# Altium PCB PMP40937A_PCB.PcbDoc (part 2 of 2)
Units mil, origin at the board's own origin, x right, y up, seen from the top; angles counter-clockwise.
Board outline 1377.95 x 1377.95 mil, 2 copper layers (Top Layer, Bottom Layer), stack 62 mil thick; 90 components, 42 nets, 235 pads, 300 vias.
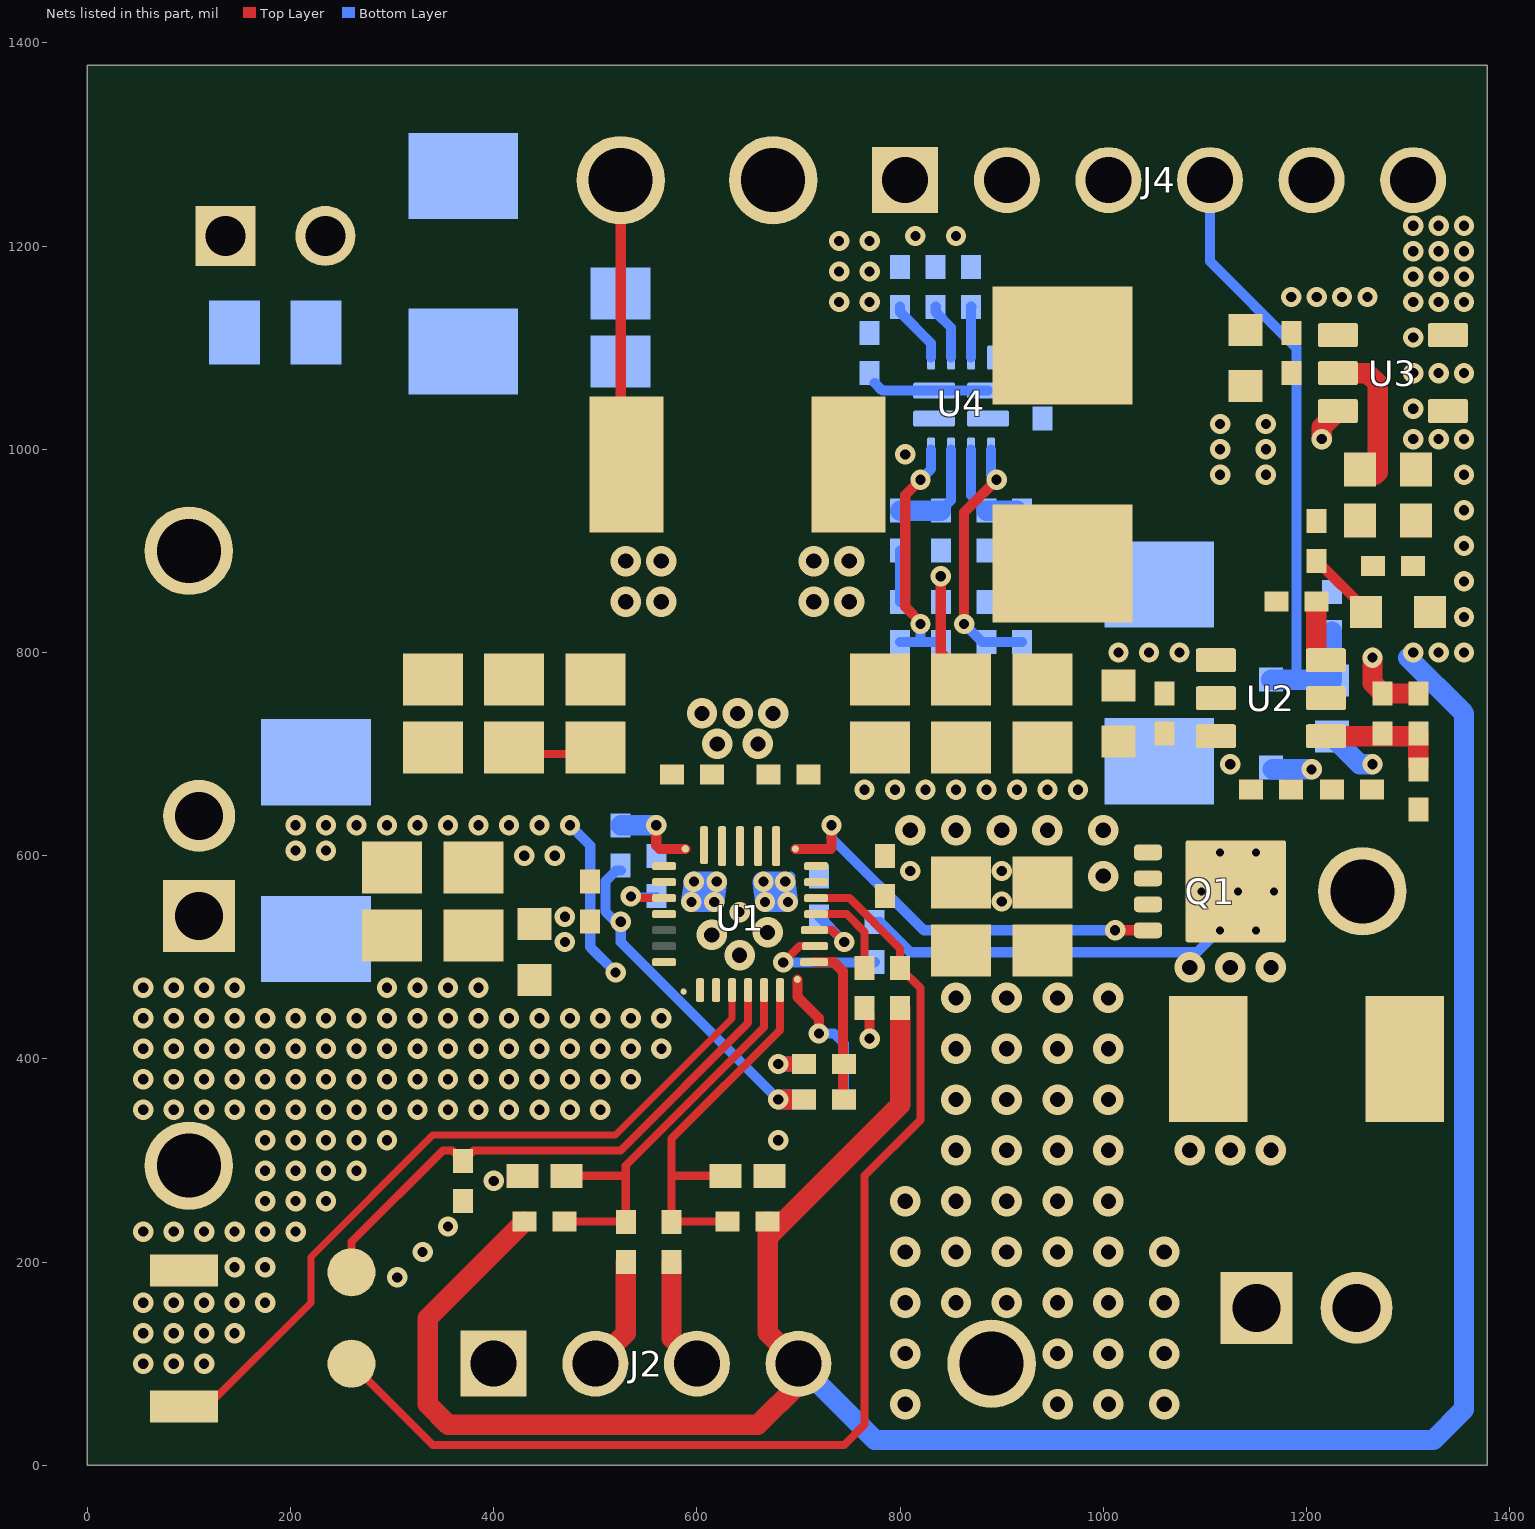
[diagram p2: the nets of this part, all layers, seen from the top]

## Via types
v1: diameter 20, hole 10, Top Layer to Bottom Layer, tented both sides, 199 vias
v2: diameter 30, hole 15, Top Layer to Bottom Layer, tented both sides, 63 vias
v3: diameter 20, hole 10, Top Layer to Bottom Layer, tented top, 13 vias
v4: diameter 19.68, hole 7.87, Top Layer to Bottom Layer, 6 vias
v5: diameter 20, hole 10, Top Layer to Bottom Layer, tented bottom, 6 vias
v6: diameter 30, hole 15, Top Layer to Bottom Layer, tented top, 6 vias
v7: diameter 20, hole 10, Top Layer to Bottom Layer, 4 vias
v8: diameter 19.68, hole 7.87, Top Layer to Bottom Layer, tented both sides, 1 vias
v9: diameter 30, hole 15, Top Layer to Bottom Layer, tented bottom, 1 vias
v10: diameter 30, hole 15, Top Layer to Bottom Layer, 1 vias

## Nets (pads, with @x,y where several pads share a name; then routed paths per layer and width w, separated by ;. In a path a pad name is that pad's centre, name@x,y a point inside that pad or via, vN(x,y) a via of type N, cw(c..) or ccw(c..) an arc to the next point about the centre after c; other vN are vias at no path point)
3.3V: C25.1 C26.1 C27.2 D8.2 J2.4 J4.6 R5.1 R6.1 R11.1 U3.4 U3.5 | length 2522.8
  Top Layer w20: R6.1@430.32,240 335,144.68 335,60 355,40 660,40 700,80 J2.4@700,100 669.68,130.32 669.68,224.68 ; R5.1@669.68,240 669.68,224.68 ; R11.1@800,450.32 800,355 669.68,224.68
  Bottom Layer w20: J2.4@700,100 775,25 1325,25 1355,55 1355,740 v1@1300,795
  other v1: 1305,800 1330,800 1355,835 1355,870 1355,905 1355,940 1355,975 1305,1010 1330,1010 1355,1010 1305,1040 1305,1075 1330,1075 1355,1075 1305,1110 1305,1145 1330,1145 1355,1145 1305,1170 1330,1170 1305,1195 1330,1195 1305,1220 1330,1220 1355,1220
  other v3: 1355,800
  other v7: 1355,1170 1355,1195
5V: C22.1 C23.1 C24.2 J4.5 L2.2 R21.1 U3.1 U3.3 | length 112.8
  Top Layer w10: U3.3@1230.87,1033.46 U3.3@1230.87,1037.6
  Top Layer w20: v1(1215,1010) 1215,1021.73 U3.3@1230.87,1037.6 ; v3(1265,795) 1265,769.68 C22.1@1275,759.68 R21.1@1310,759.68
  other v1: 1235,1150
  other v3: 1260,1150
  other v5: 1185,1150 1210,1150
CE: pad.1@260,190 R7.1 U1.13 | length 550.8
  Top Layer w8: pad.1@260,190 260,220 350,310 359.37,310 R7.1@369.68,299.68 ; R7.1@370,299.68 R7.1@369.68,299.68 ; U1.13@650.37,467.7 650.37,435.37 525,310 380,310 R7.1@369.68,299.68
INT: pad.2@260,100 R11.2 U1.21 | length 1149.2
  Top Layer w8: pad.2@260,100 340,20 745,20 765,40 765,285 820,340 820,469.69 R11.2@800,489.69 800,508.38 750.14,558.25 U1.21@717.3,558.25
NetC9_1: C9.1 L1.2 TP3.1 U1.28 | length 369.1
  Top Layer w10: TP3.1@525,1265 525,990.75 L1.2@530.75,985
  Bottom Layer w10: v1@593.12,577 v1@594.5,577
  Bottom Layer w20: v1(594.5,554.5) v1(597,574.5) v1(619.5,574.5) v1(617,554.5) v1(594.5,554.5)
  other v2: 530,850 565,850 530,890 565,890
NetC9_2: C9.2 U1.4 | length 62.8
  Top Layer w8: v1@530,558.25 U1.4@567.7,558.25
  Bottom Layer w8: v1(535,560) 559.69,560 C9.2@560,560.31
NetC10_1: C10.1 L1.1 U1.26 | length 92.6
  Bottom Layer w10: v1(687,574.5) v1@692.18,579.68
  Bottom Layer w20: v1@664.5,574.5 v1(667,554.5) v1(689.5,554.5) v1(687,574.5) v1@664.5,574.5
  other v1: 665.5,574.5
  other v2: 715,850 715,890 750,890
  other v6: 750,850
NetC10_2: C10.2 U1.19 | length 70.3
  Top Layer w8: U1.19@715.73,526.75 732.99,526.75 744.75,515 v1(745,515)
  Bottom Layer w10: C10.2@720,540.31 745.31,515 v1(745,515)
NetC11_2: C11.2 C12.1 C13.1 Q1.1 Q1.2 Q1.3 U1.22 U1.23
  other v1: 900,555 810,585 900,585
  other v2: 810,625 945,625 1000,625
  other v6: 1000,580 855,625 900,625
NetC21_1: C21.1 L2.1 U2.2
NetC21_2: C21.2 U2.6 | length 53.1
  Top Layer w20: U2.6@1209.68,791.85 C21.2@1209.68,845
NetC22_2: C22.2 R20.2 R21.2 U2.4 | length 113.8
  Top Layer w20: U2.4@1219.13,717.6 R21.2@1302.28,717.6 ; R20.2@1310,689.69 R21.2@1310,720.31
NetC31_2: C31.2 U4.11 | length 50.1
  Bottom Layer w10: U4.11@869.84,1090.28 869.84,1140.16 C31.2@870,1140.31
NetC32_2: C32.2 C33.1 J3.2 pad.1@370,1096.26 pad.2@225,1115 U4.1 U4.8 | length 114.7
  Bottom Layer w10: C32.2@775,1065.32 782.52,1057.8 U4.8@833.43,1057.8 U4.1@886.57,1057.8
NetD5_1: D5.1 R4.2 R5.2 U1.15 | length 380.6
  Top Layer w8: R4.2@575,239.69 575,285 ; R4.2@575.31,240 R5.2@630.31,240 ; D5.1@628.35,285 575,285 ; U1.15@681.87,467.7 681.87,428.74 681,427.87 681,427.62 575,321.62 575,285
NetD6_1: D6.1 R3.2 R6.2 U1.14 | length 402.7
  Top Layer w8: R6.2@469.69,240 R3.2@529.69,240 ; D6.1@471.65,285 530,285 ; R3.2@530,239.69 530,285 ; U1.14@666.12,467.7 666.12,431.12 530,295 530,285
NetD7_2: D7.2 R17.1 R18.2 U2.5 | length 38.3
  Bottom Layer w20: D7.2@1166.69,685 v1(1205,685)
NetD8_1: D8.1 R22.1 | length 71.2
  Top Layer w10: R22.1@1210.16,890.32 D8.1@1260.47,840
NetF1_1: F1.1 J5.2
NetJ2_2: J2.2 R3.1 | length 112.7
  Top Layer w20: J2.2@500,100 530,130 R3.1@530,200.32
NetJ2_3: J2.3 R4.1 | length 110.7
  Top Layer w20: R4.1@575,200.32 575,125 J2.3@600,100
NetQ1_4: Q1.4 U1.24 | length 421
  Top Layer w10: U1.24@696.88,606.72 731.72,606.72 732.5,607.5 v3(732.5,630) ; v3(1011.61,526.61) Q1.4@1044.96,526.61
  Bottom Layer w10: v3(732.5,630) 732.5,617.5 823.39,526.61 v3(1011.61,526.61)
NetR1_1: R1.1 R2.2 U1.17 | length 158.3
  Top Layer w10: U1.17@715.33,495.26 734.74,495.26 743.62,486.38 R1.1@743.62,360
NetR8_1: R8.1 U1.20 | length 90.3
  Top Layer w8: U1.20@717.3,542.5 747.5,542.5 765,525 R8.1@765,489.68
NetR9_1: R9.1 U1.18 | length 128.1
  Top Layer w8: v1(685,495) 701,511 U1.18@716.32,511
  Bottom Layer w10: v1(685,495) 774.68,495 R9.1@775,495.32
NetR10_2: R10.2 U1.1 | length 80.5
  Top Layer w10: v3@560,625 560,610 563.28,606.72 U1.1@588.61,606.72
  Bottom Layer w10: v3@559.69,624.69 v3@560,625
  Bottom Layer w20: R10.2@525,629.69 525.31,630 v3(560,630)
NetR12_1: R12.1 R13.2 U1.16 | length 146.1
  Top Layer w10: U1.16@698.85,478.28 698.85,461.15 720,440 v1(720,425)
  Bottom Layer w10: v1(720,425) 735,425 744.68,415.32 R12.1@744.68,360
NetR24_2: R24.2 R25.1 U4.6 | length 249.2
  Top Layer w10: v1@820,825 v1(820,828) 820,830 805,845 805,955 v1(820,970)
  Bottom Layer w10: R24.2@800,810.31 820,810.31 ; v1(820,828) 820,810.31 ; v1(820,970) 830.47,980.47 U4.6@830.47,999.72 ; R25.1@840,810.32 820,810.31
NetR26_2: R26.2 R27.1 U4.3 | length 251.6
  Top Layer w10: v1(863,828) 863,938 v1(895,970)
  Bottom Layer w10: v1(863,828) 880.68,810.32 R27.1@885,810.32 R26.2@920,810.31 ; U4.3@889.53,999.72 889.53,975.47 v1(895,970)
NetR28_1: R28.1 R29.2 U4.4 | length 96.3
  Bottom Layer w10: U4.4@869.84,999.72 869.84,954.84 R29.2@885,939.69
  Bottom Layer w20: R29.2@885,939.69 R28.1@915,939.69
NetR30_2: R30.2 R31.2 U4.5 | length 104.2
  Bottom Layer w10: R31.2@840,939.69 850.16,949.84 U4.5@850.16,999.72
  Bottom Layer w20: R30.2@800,939.69 R31.2@840,939.69
NetR32_2: R32.2 U4.9 | length 62.7
  Bottom Layer w10: R32.2@800,1140.31 800,1135 830.47,1104.53 U4.9@830.47,1090.28
NetR33_2: R33.2 U4.10 | length 56.3
  Bottom Layer w10: R33.2@835,1140.31 835,1135 850.16,1119.84 U4.10@850.16,1090.28
PGND: C1.2 C2.2 C3.1 C4.2 C5.2 C6.2 C7.1 C8.1 C11.1 C12.2 C13.2 C14.1 C15.2 C16.2 C17.2 C18.2 C19.1 C20.2 C23.2 C24.1 C25.2 C26.2 C27.1 C29.1 C30.1 C31.1 C32.1 C33.2 D1.2 D2.2 D5.2 D6.2 J1.1 J2.1 J3.1 J4.1 J4.3 J5.1 pad.1@145,1115 pad.2@370,1269.02 R2.1 R7.2 R8.2 R13.1 R18.1 R20.1 R22.2 R25.2 R27.2 R29.1 R31.1 R32.1 R33.1 S1.1 TP2.1 TP6.1 U1.10 U1.11 U1.27 U2.1 U3.2 U4.12 | length 351.4
  Top Layer w10: R8.2@765,450.31 770,445.31 v1(770,420) ; v1(840,875) 840,800 C16.2@860,780
  Top Layer w15: v1(680,395) R2.1@695,395
  Top Layer w20: U3.2@1230.87,1075 1260,1075 1270,1065 1270,977.56 C25.2@1267.44,975
  Bottom Layer w15: v1(680,395) R13.1@695,395
  Bottom Layer w20: C20.2@1225,717.44 1252.44,690 v1(1265,690)
  other v1: 85,100 115,100 85,130 115,130 145,130 55,160 85,160 115,160 145,160 175,160 305,185 145,195 175,195 330,210 55,230 85,230 115,230 145,230 175,230 205,230 355,235 175,260 205,260 235,260 400,280 175,290 205,290 235,290 265,290 175,320 205,320 235,320 265,320 295,320 680,320 55,350 85,350 115,350 145,350 175,350 205,350 235,350 265,350 295,350 325,350 355,350 385,350 415,350 445,350 475,350 505,350 85,380 115,380 145,380 175,380 205,380 235,380 265,380 355,380 385,380 415,380 445,380 475,380 535,380 85,410 115,410 145,410 175,410 205,410 235,410 265,410 295,410 325,410 355,410 385,410 415,410 445,410 475,410 505,410 535,410 565,410 55,440 85,440 115,440 145,440 175,440 205,440 235,440 265,440 295,440 325,440 355,440 385,440 415,440 445,440 475,440 505,440 535,440 565,440 55,470 85,470 115,470 145,470 295,470 325,470 355,470 385,470 470,515 470,540 642,544.5 1015,800 1045,800 1075,800 1115,975 1160,975 805,995 1115,1000 1160,1000 1160,1025 740,1145 770,1145 740,1175 770,1175 740,1205 770,1205 815,1210 855,1210
  other v2: 805,60 955,60 1005,60 1060,60 805,110 955,110 1060,110 805,160 855,160 905,160 955,160 1005,160 1060,160 805,210 855,210 905,210 955,210 1005,210 1005,210 1060,210 1060,210 855,260 905,260 955,260 855,310 905,310 955,310 1005,310 855,360 905,360 955,360 1005,360 855,410 905,410 955,410 855,460 905,460 955,460 1005,460 642,502 614.5,522 669.5,524.5 620,710 660,710 605,740 640,740 675,740
  other v3: 55,100 55,130 55,380 55,410 1115,1025
  other v5: 505,380
  other v6: 1005,110 1005,260
  other v7: 295,380 325,380
  other v9: 1005,410
  other v10: 805,260
PMID: C4.1 C5.1 C6.1 C7.2 U1.29 | length 80
  Top Layer w8: C5.1@420,700 C6.1@500,700
QON: S1.2 U1.12 | length 767.1
  Top Layer w7: S1.2@80,58.07 118.07,58.07 220,160 220,205 340,325 520,325 634.63,439.63 U1.12@634.63,467.7
REGN: C8.2 R1.2 R10.1 R12.2 U1.5 | length 357.9
  Top Layer w20: v1(680,360) R1.2@705.31,360
  Bottom Layer w10: R10.1@525,585.32 520.32,585.32 510,575 510,545 520,535 v1(525,535) 525,515 v1(680,360)
  Bottom Layer w20: v1(680,360) R12.2@705,360
RESET: C20.1 D7.1 J4.4 R19.2 | length 633.9
  Bottom Layer w10: J4.4@1105,1265 1105,1185 1190,1100 1190,773.31
  Bottom Layer w20: D7.1@1165,773.31 1190,773.31 C20.1@1224.25,773.31 ; C20.1@1225,772.56 R19.2@1225,820.31
RST: R19.1
VBAT: F1.2 Q1.5 Q1.6 Q1.7 Q1.8 Q1.9 R9.2 TP5.1 | length 360.1
  Bottom Layer w10: R9.2@775,534.69 780.31,534.69 810,505 1092.28,505 v4@1113.9,526.61
  other v2: 1085,310 1125,310 1165,310 1085,490 1125,490 1165,490
  other v4: 1114.65,526.61 1150.28,526.61 1096.83,565 1132.46,565 1114.65,603.39 1150.28,603.39
  other v8: 1168.09,565
VBUS: C1.1 C2.1 C3.2 C29.2 D1.1 J1.2 R24.1 R30.1 TP1.1 U1.2 U1.3 U1.8 U1.9 U4.7 | length 219.3
  Bottom Layer w10: v5(460,600) v5@465,600 ; v1(475,630) 495,610 495,570 495,510 v1(520,485) ; R24.1@800,849.68 R30.1@800,900.32
  other v1: 430,600 205,605 205,630 235,630 295,630 325,630 355,630 445,630
  other v3: 385,630 415,630
  other v5: 235,605 265,630
VSYS: C14.2 C15.1 C16.1 C17.1 C18.1 C19.2 C30.2 D2.1 J4.2 R17.2 R26.1 R28.2 TP4.1 U1.25 U2.3 U4.2 | length 40.6
  Bottom Layer w20: R26.1@920,859.68 R28.2@920,900.31
  other v1: 765,665 795,665 825,665 855,665 885,665 915,665 945,665 975,665 1125,690
pads on no net: Q1.9A Q1.9B Q1.9C Q1.9D U1.6 U1.7
copper on no net: | length 50.3
  Top Layer w10: 1210,890.32 1210.16,890.32
  Bottom Layer w10: 869.84,1090.28 869.84,1140.16 870,1140.32

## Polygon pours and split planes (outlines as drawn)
PGND on Bottom Layer "Bottom Layer-No Net" (solid, pour order 0): 1185,215 1185,240 1175,250 1070,250 1050,270 1050,580 0,580 0,0 1040,0 1185,0
PGND on Top Layer "Top Layer-PGND" (solid, pour order 2): 600,820 745,675 745,0 445,0 0,0 0,1377.95 470,1377.95 470,835 485,820

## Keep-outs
Keep-Out Layer:
  lines w10: -5,3000 cw(c0,3000) 0,3005 ccw(c0,3000) -5,3000
  text ".Layer_Name" at 577,-858.49 h60

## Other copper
Top Layer:
  region net 5V: 1250,1310 1250,1355 1240,1365 1170,1365 1160,1355 1160,1310 1160,1240 1080,1160 1065,1160 890,1160 875,1145 875,1060 890,1045 1065,1045 1120,1100 1270,1100 1275,1105 1275,1160 1250,1185 1250,1295
  region net NetC21_1: 890,830 880,840 880,935 895,950 1095,950 1185,860 1185,770 1160,745 1090,745 1085,750 1085,765 1090,770 1140,770 1145,775 1145,820 1135,830
  region net VBAT: 1185,290 1175,280 1060,280 1050,290 1050,310 1050,490 1075,515 1075,630 1085,640 1255,640 1275,620 1355,620 1365,610 1365,515 1355,505 1235,505 1185,455
  region net PGND: 310,745 300,735 300,805 315,820 800,820 810,810 830,810 835,815 835,840 820,855 820,945 835,960 835,980 830,985 800,985 795,990 795,1070 725,1140 725,1205 750,1230 750,1305 760,1315 845,1315 850,1310 850,1230 870,1210 955,1210 965,1220 965,1355 975,1365 1040,1365 1050,1355 1050,1310 1050,1195 1030,1175 880,1175 860,1155 860,1057.5 885,1032.5 885,985 875,975 875,965 850,940 850,845 845,840 845,815 850,810 870,810 880,820 1125,820 1135,810 1135,805 1135,785 1130,780 1085,780 1075,770 1075,750 1070,745 730,745 684.9,699.9 684.8,664.8 650,630 650,550 660,540 690,540 695,535 695,520 685,510 678,510 669,501 669,487 667,485 653,485 629,485 625,481 625,445 518.76,338.76 514.3,338.76 598,422.47 598,467 598,487 585,500 585,539 623,539 635,551 635,630 625,640 600,665 600,695 550,745
  region net PMID: 565,650 580,635 595,635 600,630 600,590 615,590 615,640 590,665 590,695 550,735 315,735 310,730 310,675 320,665 530,665 545,650
  region net VSYS: 725,650 710,635 690,635 685,630 685,590 670,590 670,640 695,665 695,700 730,735 1155,735 1160,730 1160,655 1155,650
  region net NetC9_1: 618,585 620,587 620,625 630,625 630,554 621,545 590,545 585,550 585,580 590,585
  region net NetC10_1: 665,587 668,584 696,584 700,580 700,550 695,545 663,545 655,553 655,625 665,625
  region net VBUS: 310,655 205,655 190,640 190,600 225,565 230,560 420,560 510,560 525,575 542.5,575 547.5,570 580,570 580,595 545,595 535,605 535,645 525,655 485,655
  region net NetC11_2: 785,640 760,640 755,635 755,610 740,595 705,595 705,570 760,570 770,580 795,580 830,545 1055,545 1060,550 1060,635 1055,640
  region net NetC9_1: 520,1095 530,1095 550,1075 590,1075 600,1065 600,840 590,830 500,830 490,840 490,1055 490,1065
  region net NetC10_1: 775,1075 690,1075 680,1065 680,840 690,830 780,830 785,835 785,1065
  region net PGND: 1270,1090 1280,1080 1280,1055 1260,1055 1255,1060 1200,1060 1195,1055 1195,1000 1200,995 1230,995 1260,1025 1280,1025 1280,1000 1280,875 1260,875 1220,915 1150,915 1105,960 1105,1070 1125,1090
  region net 3.3V: 1360,780 1365,785 1365,1355 1355,1365 1275,1365 1265,1355 1265,1185 1290,1160 1290,1140 1290,1005 1290,785 1295,780 1340,780
  region net NetD7_2: 1175,650 1235,650 1240,655 1240,685 1230,695 1190,695 1185,700 1185,730 1195,740 1235,740 1240,745 1240,765 1235,770 1200,770 1170,740 1170,655
  region net PGND: 1315,630 1320,630 1325,635 1325,655 1320,660 1295,660 1285,670 1285,695 1280,700 1255,700 1250,695 1250,660 1280,630
  region net NetR10_2: 593.29,626.71 578.29,626.71 565,640 550,640 545,635 545,610 553.45,601.55 591.71,601.55 593.29,603.13
  region net NetQ1_4: 692.01,627.01 712.01,627.01 725,640 740,640 745,635 745,610 736.7,601.7 692.93,601.7 692.01,602.41
  region net PGND: 755,420 765,410 775,410 780,415 780,460 775,465 755,465
  region net NetJ2_2: 455,205 460,210 545,210 545,60 455,60
  region net NetJ2_3: 635,60 645,70 645,205 640,210 565,210 565,60
  region net 3.3V: 735,30 750,45 750,290 740,300 660,220 660,30
  region net PGND: 780,25 790,15 1175,15 1185,25 1185,250 1175,260 1050,260 1030,280 1030,480 975,535 830,535 790,575 775,575 765,565 765,560 830,495 830,330 780,280
  region net NetR12_1: 700,415 693.68,421.32 693.68,481.48 695.65,483.44 727.96,483.44 730,481.41 730,420 725,415
  region net VSYS: 865,1240 880,1225 935,1225 945,1235 945,1355 935,1365 635,1365 620,1350 620,1225 630,1215 710,1215 730,1235 730,1310 750,1330 855,1330 865,1320
  region net VBUS: 557.61,475 515,475 510,480 510,490 520,500 577.5,500 580,497.5 580,495 590,485 590,460 584.11,460 584.11,465.89 575,475
  region net REGN: 425,460 420,465 420,490 425,495 490,495 515,520 515,535 520,540 540,540 546,546 580,546 580,538 548,538 490,480 475,480 455,460
  region net NetF1_1: 1250,475 1215,440 1215,220 1215,25 1225,15 1350,15 1365,30 1365,295 1365,465 1355,475
  text ".Layer_Name" at 577,-858.49 h60
Bottom Layer:
  region net PGND: 560,510 595,475 600,475 640,475 675,510 700,510 715,510 700,525 700,535 695,540 660,540 650,550 650,665 690,705 690,815 685,820 595,820 590,815 590,710 635,665 635,550 625,540 560,540 545,540 545,525
  pour cut-out: 487.5,980 790,980 790,702.5 487.5,702.5
  region net NetC9_1: 550,585 545,590 545,605 550,610 565,610 580,625 580,640 510,710 510,910 515,915 580,915 585,910 585,705 630,660 630,554 621,545 590,545 580,555 580,575 570,585
  region net NetC10_1: 695,545 715,565 730,565 735,570 735,590 710,615.36 710,640 770,700 770,900 755,915 700,915 695,910 695,700 655,660 655,555 665,545
  region net VSYS: 800,775 790,775 785,770 785,700 755,670 755,655 760,650 1130,650 1135,655 1135,710 1110,735 1000,735 990,745 990,1190 985,1195 955,1225 955,1295 955,1310 950,1315 865,1315 860,1310 860,1280 860,1240 930,1170 930,1115 955,1090 960,1085 960,1055 945,1040 910,1040 865,1040 865,1020 900,1020 910,1010 910,985 930,965 940,955 940,925 910,895 910,855 940,825 940,785 930,775
  region net 3.3V: 1345,710 1365,710 1365,1355 1355,1365 1275,1365 1265,1355 1265,1280 1265,1270 1265,1185 1290,1160 1290,765
  region net PGND: 1050,1310 1050,1355 1040,1365 760,1365 750,1355 750,1310 845,1310 860,1325 955,1325 965,1315 965,1295 965,1280 965,1230 1000,1195 1000,750 1005,745 1115,745 1155,705 1215,705 1260,660 1300,660 1310,670 1310,725 1295,740 1160,740 1145,755 1145,790 1175,820 1175,1075 1050,1200 1050,1285
  region net NetC11_2: 760,640 755,635 755,615 825,545 1055,545 1060,550 1060,630 1050,640
  region net VBAT: 1070,280 1080,270 1320,270 1330,280 1330,630 1320,640 1080,640 1070,630
  region net 5V: 1250,1355 1240,1365 1170,1365 1160,1355 1160,1310 1160,1295 1160,1280 1160,1155 1205,1110 1205,930 1255,880 1255,785 1260,780 1270,780 1275,785 1275,1160 1250,1185
  region net RESET: 1150,1355 1140,1365 1075,1365 1065,1355 1065,1200 1185,1080 1185,1075 1195,1085 1195,1105 1150,1150
  region net RESET: 1245,825 1235,835 1205,835 1195,845 1185,835 1185.02,815.02 1155,785 1155,760 1165,750 1240,750 1245,755
  region net RST: 1235,845 1235,885 1225,895 1215,895 1210,890 1210,850 1215,845
  region net PGND: 280,1265 340,1205 385,1205 470,1120 740,1120 760,1100 780,1100 780,1155 785,1160 880,1160 885,1155 885,1080 890,1075 910,1075 930,1055 950,1055 950,1080 915,1115 915,1165 850,1230 850,1305 850,1315 840,1315 755,1315 750,1310 750,1290 750,1230 705,1185 515,1185 470,1230 470,1355 460,1365 25,1365 15,1355 15,1120 15,1060 25,1050 165.01,1050 175,1059.99 175,1240 200,1265
  region net PGND: 830,845 895,845 895,915 830,915
  region net NetC32_2: 455,1110 375,1190 335,1190 275,1250 215,1250 195,1230 195,1060 205,1050 225,1050 905,1050 905,1065 815,1065 790,1090 755,1090 735,1110
  region net NetR24_2: 790,785 785,790 785,825 805,825 810,830 840,830 850,820 850,790 845,785
  region net VBUS: 790,835 785,840 785,900 735,950 735,972.5 735,980 725,990 510,990 500,980 500,570 495,570 305,570 280,570 260,590 15,590 15,1030 25,1040 760,1040 855,1040 855,1020 820,1020 765,1020 750,1005 750,955 790,915 810,915 810,840 805,835
  pour cut-out: 745,1025 760,1040 745,1025
  region net PGND: 760,1000 770,1010 810,1010 815,1005 815,990 805,980 805,965 800,960 765,960 760,965
  region net NetR32_2: 830,1075 835,1080 835,1105 810,1130 810,1150 790,1150 790,1105 820,1075
  region net NetR26_2: 925,785 930,790 930,820 925,825 880,825 870,835 860,835 860,790 865,785
  region net NetF1_1: 1315,45 1330,60 1330,200 1330,240 1320,250 1225,250 1215,240 1215,220 1215,200 1215,45
  text ".Layer_Name" at 577,-858.49 h60

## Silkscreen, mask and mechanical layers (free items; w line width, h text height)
Top Overlay:
  lines w5: 775,430 785,420 ; 810,430 820,420 ; 875,460 895,430 ; 930,460 950,430 ; 1140,870 1150,860
  text "SW1" at 470,1325 h60
  text "SYS" at 625,1325 h60
  text "SYS" at 855,1325 h60
  text "RST" at 1055,1325 h60
  text "5V" at 1175,1325 h60
  text "3.3V" at 1260,1325 h60
  text "PGND" at 35,1320 h60
  text "VBDC" at 215,1320 h60
  text "+" at 350,1175 h100
  text "VBUS" at 225,830 h60 r90
  text "+" at 85,740 h100
  text "PGND" at 185,295 h60
  text "\CE" at 215,230 h60
  text "_" at 1135,45 h80
  text "PGND" at 1025,40 h60 r90
  text "INT" at 230,20 h60
  text "+" at 1235,10 h80
  text "+" at 685,0 h80
Bottom Overlay:
  rectangle: 945,1315 1040,1365
  lines w8: 335,1045 405,1045 ; 725,920 765,920 ; 740,1160 780,1160 ; 920,1005 945,980 ; 495,750 715,750 715,975 495,975 495,750 ; 775,785 775,960 945,960 945,785 775,785
  text "VBDC" at 260,1320 h60
  text "SW1" at 585,1320 h60
  text "SYS" at 725,1320 h60
  text "PGND" at 895,1320 h60
  text "'.PRJ_Number'.PCB_Rev-" at 1365,1320 h60
  text "_" at 160,1285 h100
  text "+" at 255,1245 h100
  text "5V" at 1185,1155 h60 r270
  text "SYS" at 890,1115 h60 r270
  text "RST" at 1085,1115 h60 r270
  text "3.3V" at 1285,1110 h60 r270
  text "PGND" at 985,1070 h60 r270
  text "VBUS" at 175,970 h60
  text "+" at 135,680 h100
  text "VBAT" at 1330,470 h60
  text "PACK" at 1275,270 h60
  text "_" at 1175,250 h80
  text "+" at 1265,215 h80
  text "PGND" at 170,195 h60
  text "PGND" at 965,155 h60
  text "PGND" at 380,150 h60 r270
  text "SCL" at 480,150 h60 r270
  text "SDA" at 580,150 h60 r270
  text "3.3V" at 680,150 h60 r270
  text ".Layer_Name" at 577,-858.49 h60
Top Paste:
  text ".Layer_Name" at 577,-858.49 h60
Bottom Paste:
  text ".Layer_Name" at 577,-858.49 h60
Top Solder:
  text ".Layer_Name" at 577,-858.49 h60
  text ".Layer_Name" at 577,-858.49 h60
Bottom Solder:
  text ".Layer_Name" at 577,-858.49 h60
Drill Guide:
  text ".Layer_Name" at 577,-858.49 h60
M1 Board Outline:
  the board outline again, w10
  text ".Layer_Name" at 577,-858.49 h60
M2 Board Dimensions:
  rectangle: 0,-275 125,-150
  rectangle: 125,-400 500,-275
  lines w7: 0,-275 1000,-275 ; 125,-400 125,-150 ; 250,-400 250,-150 ; 500,-400 500,-150 ; 750,-400 750,-150 ; 0,-400 1000,-400 1000,-150 0,-150 0,-400
  text ".Layer_Name" at 577,-858.49 h60
M3 3D STEP Top:
  text ".Layer_Name" at 577,-858.49 h60
M4 3D STEP Bottom:
  text ".Layer_Name" at 577,-858.49 h60
M5 Assembly Top:
  lines w10: -292,-930.17 6308,-930.17 ; -292,-726.83 6310,-726.83 ; -292,-523.5 -292,-1133.5 3713,-1133.5 6310,-1133.5 6310,-523.5 -291.5,-523.5 -291.5,-1133.5 1284,-1133.5 ; 2173,-1133.5 2173,-523.5 ; 3440,-726.83 3440,-523.5 ; 4280,-726.83 4280,-523.5 ; 4902,-1140 4902,-937.17
  text "COMPONENTS MARKED 'DNP' SHOULD NOT BE POPULATED." at 1153.5,-318.5 h60
  text "ASSEMBLY VARIANT:" at 1153,-434 h60
  text ".VariantName" at 2189,-434 h60
  text "PCB VIEWED FROM TOP SIDE" at -228.5,-655.67 h60
  text "BOARD #:" at 2248,-655.67 h60
  text ".PRJ_Number" at 2793.5,-655.67 h60
  text "REV:" at 3638,-655.67 h60
  text ".PCB_Rev" at 3929.5,-655.67 h60
  text "SVN REV:" at 4476,-655.67 h60
  text ".VersionControl_RevNumber" at 4982,-655.67 h60
  text "TID #:" at 2248,-859 h60
  text ".TID" at 2793.5,-859 h60
  text "PLOT NAME =" at -228.5,-1064.34 h60
  text ".plot_File_Name" at 577,-1064.34 h60
  text "GENERATED    :" at 2250,-1064.34 h60
  text ".Print_Date" at 3119.5,-1064.34 h60
  text ".Print_Time" at 3848.5,-1064.34 h60
  text "TEXAS INSTRUMENTS" at 5113,-1064.34 h60
M6 Assembly Bottom:
  lines w10: -292.5,-727.33 6309.5,-727.33 ; -290.5,-930.67 6309.5,-930.67 ; 1115.5,-1140.5 1115.5,-937.67 ; 1737.5,-727.33 1737.5,-524 ; 2577.5,-727.33 2577.5,-524 ; 3844.5,-1134 3844.5,-524 ; 4733.5,-1134 6309,-1134 6309,-524 -292.5,-524 -292.5,-1134 2304.5,-1134 6309.5,-1134 6309.5,-524
  text "COMPONENTS MARKED 'DNP' SHOULD NOT BE POPULATED." at 6102,-318 h60
  text ".VariantName" at 5058,-434 h60
  text "ASSEMBLY VARIANT:" at 6097,-434 h60
  text ".VersionControl_RevNumber" at 1035.5,-656.17 h60
  text "SVN REV:" at 1541.5,-656.17 h60
  text ".PCB_Rev" at 2088,-656.17 h60
  text "REV:" at 2379.5,-656.17 h60
  text ".PRJ_Number" at 3224,-656.17 h60
  text "BOARD #:" at 3769.5,-656.17 h60
  text "PCB VIEWED FROM BOTTOM SIDE" at 6246,-656.17 h60
  text ".TID" at 3224,-859.5 h60
  text "TID #:" at 3769.5,-859.5 h60
  text "TEXAS INSTRUMENTS" at 904.5,-1064.84 h60
  text ".Print_Time" at 2169,-1064.84 h60
  text ".Print_Date" at 2898,-1064.84 h60
  text "GENERATED    :" at 3767.5,-1064.84 h60
  text ".plot_File_Name" at 5440.5,-1064.84 h60
  text "PLOT NAME =" at 6246,-1064.84 h60
M9 Title Sheet:
  drawing of 152 lines, arcs and shapes, not listed
  text "1" at 739.84,8036.5 h70
  text "2" at 3235.5,8036.5 h70
  text "3" at 5724.84,8036.5 h70
  text "4" at 8231.51,8036.5 h70
  text "5" at 10730.5,8036.5 h70
  text "6" at 13235.5,8036.5 h70
  text "A" at -416.5,6893.5 h70
  text "A" at 14383.5,6893.5 h70
  text "B" at -416.5,4513.5 h70
  text "B" at 14383.5,4513.5 h70
  text "C" at -416.5,2138.5 h70
  text "C" at 14383.5,2138.5 h70
  text "PROJECT TITLE:" at 11343.5,277.5 h45
  text ".PRJ_Title" at 11393.5,144.17 h70
  text "DESIGNED FOR:" at 11343.5,-23.5 h45
  text ".PRJ_Customer" at 11393.5,-163.5 h70
  text "D" at -416.5,-231.5 h70
  text "D" at 14383.5,-231.5 h70
  text "FILE NAME:" at 11343.5,-323.5 h45
  text ".PCB_File_Name_No_Path" at 11393.5,-443.5 h70
  text "Texas Instruments (TI) and/or its licensors do not warrant the accuracy or completeness of this specification" at 6374,-605.34 h45
  text "ENGINEER:" at 11343.5,-613.5 h45
  text "LAYOUT BY:" at 12848.5,-613.5 h45
  text "or any information contained therein. TI and/or its licensors do not warrant that this design will meet" at 6329.01,-718 h45
  text ".PRJ_Engineer" at 11393.5,-768.49 h70
  text "JMM" at 12852,-800 h100
  text "s  o  l  u  t  i  o  n  s" at 13710,-803 h68
  text "the specifications, will be suitable for your application or fit for any particular purpose, or will operate in" at 6329.01,-830.67 h45
  text ".Layer_Name" at 577,-858.49 h60
  text "ALTIUM DESIGNER VERSION:" at 12848.5,-923.5 h45
  text "an implementation. TI and/or its licensors do not warrant that the design is production worthy. You should" at 6329.01,-943.33 h45
  text "completely validate and test your design implementation to confirm the system functionality for your application." at 6374,-1056 h45
  text ".print_Scale" at 11393.5,-1056.83 h70
  text ".Application_BuildNumber" at 12899,-1056.83 h70
  text "1" at 739.84,-1263.5 h70
  text "2" at 3235.5,-1263.5 h70
  text "3" at 5724.84,-1263.5 h70
  text "4" at 8231.51,-1263.5 h70
  text "5" at 10730.5,-1263.5 h70
  text "6" at 13235.5,-1263.5 h70
M10 Fab Notes:
  drawing of 173 lines, arcs and shapes, not listed
  text "DESIGN INFORMATION" at 12378.02,6201 h60
  text "MIN. TRACK WIDTH:" at 11733.46,6021 h60
  text "6" at 12829.7,6021 h60
  text "MIL" at 12984.46,6021 h60
  text "MIN. CLEARANCE:" at 11733.46,5889 h60
  text "5.7" at 12769.7,5889 h60
  text "MIL" at 12984.46,5889 h60
  text "MIN. VIA PAD SIZE:" at 11733.46,5757 h60
  text "10" at 12799.71,5757 h60
  text "MIL" at 12984.46,5757 h60
  text "0.05mm (2MIL)" at 12428.46,5615.29 h60
  text "MINIMUM ANNULAR RING" at 11404.23,5611 h60
  text "EXTERNAL" at 13136.46,5611 h60
  text "PER" at 11604.23,5493 h60
  text "IPC-D-275 CLASS 2 LEVEL C" at 11824.23,5493 h60
  text "MIL, HOLES" at 13312.46,5380.71 h60
  text "+/-" at 12920,5380 h60
  text "+/-" at 13774,5380 h60
  text "REGISTRATION TOLERANCES:" at 11404.23,5375 h60
  text "METAL" at 12604,5375 h60
  text "5" at 13180.2,5375 h60
  text "3" at 14013.2,5375 h60
  text "MIL" at 14129.46,5375 h60
  text "+/-" at 13774,5262 h60
  text "HOLE SIZE TOLERANCE (UNLESS OTHERWISE SPECIFIED):" at 11404.23,5257 h60
  text "3" at 14013.2,5257 h60
  text "MIL" at 14129.46,5257 h60
  text "MATERIAL:" at 11329.46,5047.54 h60
  text "FR-4 High Tg" at 12315.9,4907.21 h60
  text "FR-408" at 11750.46,4898.64 h60
  text "OTHER" at 13238.46,4898.64 h60
  text "X" at 12161,4895 h60
  text "X" at 11962.5,4755 h60
  text "62 MIL (1.6mm) +/-10%" at 12070.56,4735.92 h60
  text "THICKNESS:" at 11404.23,4731.64 h60
  text "OTHER" at 13355.46,4731.64 h60
  text "31 MIL +/-10%" at 13645.56,4730.92 h60
  text "TOLERANCE:" at 11404.23,4573.64 h60
  text "X" at 12243.53,4573.64 h60
  text "ANSI IPC-6012 TYPE 3 CLASS 2" at 12430.48,4573.64 h60
  text "OTHER +/-" at 12430.46,4417.64 h60
  text "BOW & TWIST:" at 11404.23,4260.64 h60
  text "X" at 12243.53,4260.64 h60
  text "ANSI IPC-6012 TYPE 3 CLASS 2" at 12430.48,4260.64 h60
  text "OTHER +/-" at 12430.46,4102.13 h60
  text "DRILLING:" at 11329.46,3963.64 h60
  text "REFERENCE:" at 11404.23,3846.64 h60
  text "X" at 12052.46,3846.64 h60
  text "AS SHOWN" at 12239.46,3846.64 h60
  text "X" at 12953.46,3846.64 h60
  text "NC_DRILL FILES" at 13090.46,3846.64 h60
  text "PTH MIN COPPER THICKNESS:" at 11404.23,3688.64 h60
  text "X" at 12754.46,3688.64 h60
  text "1MIL" at 12891.46,3688.64 h60
  text "OTHER" at 13388.46,3688.64 h60
  text "BOARD FINISH:" at 11329.46,3529.64 h60
  text "SILKSCREEN:" at 11484.68,3411.64 h60
  text "X" at 12433.46,3411.64 h60
  text "TOP" at 12559.46,3411.64 h60
  text "X" at 12943.46,3411.64 h60
  text "BOTTOM" at 13070.46,3411.64 h60
  text "SILKSCREEN COLOR:" at 11484.68,3244.64 h60
  text "X" at 12432.42,3244.64 h60
  text "WHITE" at 12559.46,3244.64 h60
  text "OTHER" at 13070.46,3244.64 h60
  text "X" at 12563.42,3085.44 h60
  text "GREEN" at 12690.46,3085.44 h60
  text "OTHER" at 13308.46,3085.44 h60
  text "SOLDER RESIST COLOR:" at 11484.68,3074.64 h60
  text "X" at 12563.42,2915.44 h60
  text "MATTE" at 12690.46,2915.44 h60
  text "SEMI-GLOSS" at 13308,2914.8 h60
  text "IMMERSION GOLD (ENIG)" at 12390.46,2726.92 h60
  text "ENEPIG" at 13728,2723.64 h60
  text "SURFACE FINISH:" at 11329.46,2722.64 h60
  text "X" at 12203.51,2722.64 h60
  text "IMM. TIN/SILVER OR EQUIV" at 11659,2565.64 h60
  text "OTHER" at 13090.46,2565.64 h60
  text "ARRAY/PANEL:" at 11329.46,2386.64 h60
  text "CUT AND TRIM PER M1 BOARD OUTLINE" at 12390.46,2382.35 h60
  text "N.C. ROUTE" at 12390.46,2230.64 h60
  text "X" at 13069.46,2230.64 h60
  text "V. SCORE" at 13256.46,2230.64 h60
  text "CERTIFICATION:" at 11329.46,2093.64 h60
  text "MATERIALS AND WORKMANSHIP FOR ALL PCBS" at 12054.46,2093.64 h60
  text "TO MEET OR EXCEED THE REQUIREMENTS OF:" at 12054.46,1995.64 h60
  text "X" at 11680.96,1859.13 h60
  text "ANSI IPC-A-600F CLASS ->" at 11819.96,1859.13 h60
  text "X" at 13459.02,1859.13 h60
  text "2" at 13577.96,1859.14 h60
  text "1" at 13262.96,1857.64 h60
  text "3" at 13931.96,1857.64 h60
  text "X" at 12495.02,1699.64 h60
  text "RoHS" at 12631.96,1699.64 h60
  text "OTHER" at 13276.36,1699.64 h60
  text "PER ORDER" at 13673.42,1699.64 h60
  text "ALL BOARDS MUST MEET OR EXCEED UL94-V0 REQUIREMENTS." at 11357,1534 h60
  text "PCB MUST BEAR THE UL94V-0 UL REGISTERED MATERIAL ID NUMBER" at 11357,1414 h60
  text "ADDITIONAL REQUIREMENTS:" at 11329.46,1240.64 h60
  text "MICROSECTION:" at 11404.23,1125.64 h60
  text "YES" at 12309.96,1125.64 h60
  text "REQUIRED" at 13171.46,969.49 h60
  text "BARE BOARD ELEC. TEST:" at 11404.23,966.64 h60
  text "NONE" at 12709.96,966.64 h60
  text "X" at 13044.46,966.64 h60
  text "PER ORDER" at 13763.46,966.64 h60
  text ".Layer_Name" at 577,-858.49 h60
M11 Gerber Information:
  lines w10: -292,-930.17 6308,-930.17 ; -292,-726.83 6310,-726.83 ; -292,-523.5 -292,-1133.5 3713,-1133.5 6310,-1133.5 6310,-523.5 -291.5,-523.5 -291.5,-1133.5 1284,-1133.5 ; 2173,-1133.5 2173,-523.5 ; 3440,-726.83 3440,-523.5 ; 4280,-726.83 4280,-523.5 ; 4902,-1140 4902,-937.17
  text "ALL ARTWORK VIEWED FROM TOP SIDE" at -228.5,-655.67 h60
  text "BOARD #:" at 2248,-655.67 h60
  text ".PRJ_Number" at 2793.5,-655.67 h60
  text "REV:" at 3638,-655.67 h60
  text ".PCB_Rev" at 3929.5,-655.67 h60
  text "SVN REV:" at 4476,-655.67 h60
  text ".VersionControl_RevNumber" at 4982,-655.67 h60
  text "LAYER NAME =" at -228.5,-858.49 h60
  text "TID #:" at 2248,-859 h60
  text ".TID" at 2793.5,-859 h60
  text "PLOT NAME =" at -228.5,-1064.34 h60
  text ".plot_File_Name" at 577,-1064.34 h60
  text "GENERATED    :" at 2250,-1064.34 h60
  text ".Print_Date" at 3119.5,-1064.34 h60
  text ".Print_Time" at 3848.5,-1064.34 h60
  text "TEXAS INSTRUMENTS" at 5113,-1064.34 h60
M12 Stackup:
  drawing of 191 lines, arcs and shapes, not listed
  text "Layer" at 9775.35,7735 h60
  text "Name" at 10185.26,7735 h60
  text "Material" at 11115,7735 h60
  text "Thickness" at 11974.77,7735 h60
  text "Constant" at 12624.61,7735 h60
  text "Board Layer Stack" at 13194.47,7735 h60
  text "1" at 9775.35,7615 h60
  text "Top Overlay" at 10185.26,7615 h60
  text "2" at 9775.35,7495 h60
  text "Top Solder" at 10185.26,7495 h60
  text "Solder Resist" at 11115,7495 h60
  text "0.40mil" at 11974.77,7495 h60
  text "3.5" at 12624.61,7495 h60
  text "3" at 9775.35,7375 h60
  text "Top Layer" at 10185.26,7375 h60
  text "Copper" at 11115,7375 h60
  text "1.40mil" at 11974.77,7375 h60
  text "4" at 9775.35,7255 h60
  text "Dielectric1" at 10185.26,7255 h60
  text "FR-4" at 11115,7255 h60
  text "59.20mil" at 11974.77,7255 h60
  text "4.8" at 12624.61,7255 h60
  text "5" at 9775.35,7135 h60
  text "Bottom Layer" at 10185.26,7135 h60
  text "Copper" at 11115,7135 h60
  text "1.40mil" at 11974.77,7135 h60
  text "6" at 9775.35,7015 h60
  text "Bottom Solder" at 10185.26,7015 h60
  text "Solder Resist" at 11115,7015 h60
  text "0.40mil" at 11974.77,7015 h60
  text "3.5" at 12624.61,7015 h60
  text "7" at 9775.35,6895 h60
  text "Bottom Overlay" at 10185.26,6895 h60
  text ".Layer_Name" at 577,-858.49 h60
M13 Component Bodies Top:
  text ".Layer_Name" at 577,-858.49 h60
M14 Component Bodies Bottom:
  text ".Layer_Name" at 577,-858.49 h60
M15 Courtyards Top:
  text ".Layer_Name" at 577,-858.49 h60
M16 Courtyards Bottom:
  text ".Layer_Name" at 577,-858.49 h60
Drill Drawing:
  circle w10: c1653.9,827.29 r13.28
  circle w10: c1653.9,827.29 r22.14
  circle w10: c1653.9,628.05 r22.14
  lines w10: 1631.76,749.81 1676.04,749.81 1653.9,705.53 1631.76,749.81 ; 1631.76,904.77 1676.04,904.77 1676.04,949.05 1631.76,949.05 1631.76,904.77 ; 1631.76,1015.47 1642.83,1015.47 1642.83,1004.4 1664.97,1004.4 1664.97,1015.47 1676.04,1015.47 1676.04,1037.6 1664.97,1037.6 1664.97,1048.67 1642.83,1048.67 1642.83,1037.6 1631.76,1037.6 1631.76,1015.47 ; 1631.76,1104.02 1631.76,1115.09 1642.83,1126.16 1631.76,1137.23 1631.76,1148.3 1642.83,1148.3 1653.9,1137.23 1664.97,1148.3 1676.04,1148.3 1676.04,1137.23 1664.97,1126.16 1676.04,1115.09 1676.04,1104.02 1664.97,1104.02 1653.9,1115.09 1642.83,1104.02 1631.76,1104.02 ; 1631.76,1214.71 1642.83,1214.71 1653.9,1203.64 1664.97,1214.71 1676.04,1214.71 1664.97,1225.78 1676.04,1236.85 1664.97,1236.85 1653.9,1247.92 1642.83,1236.85 1631.76,1236.85 1642.83,1225.78 1631.76,1214.71
  lines w12: 1591,576.02 4478.1,576.02 ; 1591,1273.38 4478.1,1273.38 ; 1906.63,476.4 1906.63,1373 ; 2223.82,476.4 2223.82,1373 ; 2845.56,476.4 2845.56,1373 ; 3089.88,476.4 3089.88,1373 ; 3450.22,476.4 3450.22,1373 ; 4159.73,476.4 4159.73,1373 ; 1591,476.4 4478.1,476.4 4478.1,1373 1591,1373 1591,476.4
  text "Symbol" at 1650.77,1303.26 h72
  text "Quantity" at 1936.52,1303.26 h72
  text "Finished Hole Size" at 2253.7,1303.26 h72
  text "Plated" at 2875.45,1303.26 h72
  text "Hole Type" at 3119.77,1303.26 h72
  text "Drill Layer Pair" at 3480.11,1303.26 h72
  text "Via/Pad" at 4189.62,1303.26 h72
  text "7" at 1936.52,1203.64 h60
  text "7.87mil (0.200mm)" at 2253.7,1203.64 h60
  text "PTH" at 2875.45,1203.64 h60
  text "Round" at 3119.77,1203.64 h60
  text "Top Layer - Bottom Layer" at 3480.11,1203.64 h60
  text "Via" at 4189.62,1203.64 h60
  text "222" at 1936.52,1104.02 h60
  text "10.00mil (0.254mm)" at 2253.7,1104.02 h60
  text "PTH" at 2875.45,1104.02 h60
  text "Round" at 3119.77,1104.02 h60
  text "Top Layer - Bottom Layer" at 3480.11,1104.02 h60
  text "Via" at 4189.62,1104.02 h60
  text "71" at 1936.52,1004.4 h60
  text "15.00mil (0.381mm)" at 2253.7,1004.4 h60
  text "PTH" at 2875.45,1004.4 h60
  text "Round" at 3119.77,1004.4 h60
  text "Top Layer - Bottom Layer" at 3480.11,1004.4 h60
  text "Via" at 4189.62,1004.4 h60
  text "2" at 1936.52,904.77 h60
  text "39.37mil (1.000mm)" at 2253.7,904.77 h60
  text "PTH" at 2875.45,904.77 h60
  text "Round" at 3119.77,904.77 h60
  text "Top Layer - Bottom Layer" at 3480.11,904.77 h60
  text "Pad" at 4189.62,904.77 h60
  text "10" at 1936.52,805.15 h60
  text "45.28mil (1.150mm)" at 2253.7,805.15 h60
  text "PTH" at 2875.45,805.15 h60
  text "Round" at 3119.77,805.15 h60
  text "Top Layer - Bottom Layer" at 3480.11,805.15 h60
  text "Pad" at 4189.62,805.15 h60
  text "4" at 1936.52,705.53 h60
  text "47.24mil (1.200mm)" at 2253.7,705.53 h60
  text "PTH" at 2875.45,705.53 h60
  text "Round" at 3119.77,705.53 h60
  text "Top Layer - Bottom Layer" at 3480.11,705.53 h60
  text "Pad" at 4189.62,705.53 h60
  text "6" at 1936.52,605.91 h60
  text "63.00mil (1.600mm)" at 2253.7,605.91 h60
  text "PTH" at 2875.45,605.91 h60
  text "Round" at 3119.77,605.91 h60
  text "Top Layer - Bottom Layer" at 3480.11,605.91 h60
  text "Pad" at 4189.62,605.91 h60
  text "322 Total" at 1936.52,506.28 h60
  text ".Layer_Name" at 577,-858.49 h60
Mechanical 17:
  text ".Layer_Name" at 577,-858.49 h60
Mechanical 18:
  text ".Layer_Name" at 577,-858.49 h60
Mechanical 19:
  text ".Layer_Name" at 577,-858.49 h60

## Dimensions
0,-400 to 1000,-400 on M2 Board Dimensions
0,0 to 0,1377.95 on M2 Board Dimensions
0,0 to 1377.95,0 on M2 Board Dimensions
